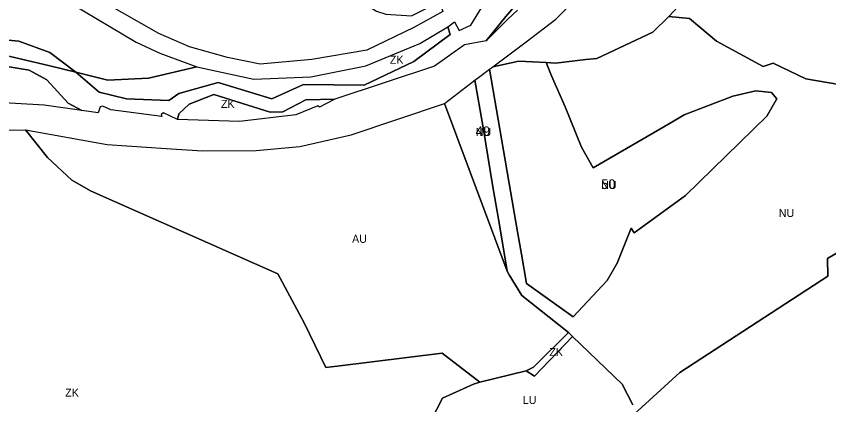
# Model space of a CAD drawing. Extents: x -521261 to -517465, y -1182764 to -1179456.
# Drawn here: x -518710 to -518203, y -1182068 to -1181825 of the extents above; entities that cross this region are included whole.
import ezdxf

# ---------------------------------------------------------------- set-up
doc = ezdxf.new("R2010")
doc.units = 0
for name, color, linetype in [('90640013', 7, 'Continuous'), ('90710013', 7, 'Continuous'), ('90730013', 7, 'Continuous'), ('90730023', 7, 'Continuous'), ('90750013', 7, 'Continuous'), ('90770013', 7, 'Continuous'), ('ID_navrh', 7, 'Continuous')]:
    doc.layers.add(name, color=color, linetype=linetype)

msp = doc.modelspace()

# ---------------------------------------------------------------- linework, layer by layer
at = {"layer": '90640013'}
for points in [[(-518715.11, -1181849.85), (-518689.48, -1181855.99), (-518673.3, -1181859.85), (-518658.65, -1181872.34), (-518641.68, -1181876.61), (-518615.19, -1181877.65), (-518608.89, -1181873.1), (-518588.11, -1181867.31), (-518584.29, -1181866.38), (-518550.76, -1181876.48), (-518531.13, -1181867.61), (-518493.06, -1181867.9), (-518462.19, -1181853.28), (-518439.36, -1181836.36), (-518440.9, -1181831.61), (-518436.68, -1181828.52), (-518433.85, -1181833.87), (-518426.44, -1181830.61), (-518418.2, -1181817.08)], [(-518399.59, -1181819.23), (-518404.75, -1181825.16), (-518417.05, -1181840.21), (-518430.51, -1181842.88), (-518449.2, -1181856.15), (-518511.46, -1181876.67), (-518529.58, -1181877.23), (-518543.87, -1181884.74), (-518551.9, -1181884.77), (-518587.12, -1181873.73), (-518602.51, -1181879.76), (-518608.97, -1181885.92), (-518609.76, -1181889.48), (-518618.56, -1181885.25), (-518619.93, -1181886.24), (-518619.44, -1181887.57), (-518651.41, -1181883.48), (-518656.4, -1181881.12), (-518658.07, -1181881.5), (-518659.19, -1181885.17), (-518669.46, -1181883.83), (-518678.12, -1181879.19), (-518691.4, -1181864.63), (-518702.42, -1181858.59), (-518732.72, -1181853.68)]]:
    msp.add_lwpolyline(points, dxfattribs=at)
at = {"layer": '90710013'}
for points in [[(-518302.96, -1181825.14), (-518312.78, -1181834.79), (-518347.83, -1181851.39), (-518354.74, -1181851.96), (-518373.71, -1181854.29), (-518379.46, -1181853.84), (-518396.5, -1181852.96), (-518412.79, -1181856.47), (-518392.04, -1181840.87), (-518373.39, -1181826.78), (-518345.1, -1181798.17), (-518320.12, -1181766.51), (-518297.97, -1181731.65), (-518284.29, -1181709.64), (-518257.78, -1181667.72), (-518268.81, -1181694.86), (-518271.03, -1181704.12), (-518273.51, -1181713.67), (-518287.7, -1181797.29), (-518296.94, -1181818.88)], [(-518673.3, -1181859.85), (-518653.23, -1181864.79), (-518627.84, -1181863.67), (-518597.74, -1181856.58), (-518562.08, -1181864.17), (-518526.41, -1181862.85), (-518492.11, -1181855.83), (-518458.32, -1181841.87), (-518440.9, -1181831.61), (-518439.36, -1181836.36), (-518462.19, -1181853.28), (-518493.06, -1181867.9), (-518531.13, -1181867.61), (-518550.76, -1181876.48), (-518584.29, -1181866.38), (-518588.11, -1181867.31), (-518608.89, -1181873.1), (-518615.19, -1181877.65), (-518641.68, -1181876.61), (-518658.65, -1181872.34)], [(-518535.85, -1181886.47), (-518570.95, -1181890.66), (-518609.76, -1181889.48), (-518608.97, -1181885.92), (-518602.51, -1181879.76), (-518587.12, -1181873.73), (-518551.9, -1181884.77), (-518543.87, -1181884.74), (-518529.58, -1181877.23), (-518511.46, -1181876.67), (-518517.15, -1181879.72), (-518520.95, -1181881.69), (-518522.17, -1181880.83)], [(-518365.6, -1182022.45), (-518363.045, -1182024.91), (-518386.67, -1182049.7), (-518391.97, -1182046.38), (-518387.41, -1182044.05)]]:
    msp.add_lwpolyline(points, close=True, dxfattribs=at)
for points in [[(-518783.87, -1181833.43), (-518708.84, -1181840.52), (-518689.43, -1181847.62), (-518673.3, -1181859.85), (-518689.48, -1181855.99), (-518715.11, -1181849.85)], [(-518928.06, -1182074.15), (-518913.53, -1182057.93), (-518918.106, -1182050.945), (-518903.79, -1182038.57), (-518884.14, -1182023.3), (-518858.18, -1181999.19), (-518833.62, -1181978.44), (-518841.96, -1181963.21), (-518740.3, -1181896.33), (-518704.59, -1181895.96), (-518690.9, -1181913.09), (-518675.7, -1181927.23), (-518663.75, -1181934.22), (-518547.12, -1181985.79), (-518530.56, -1182016.35), (-518517.09, -1182044.24), (-518510.09, -1182043.38), (-518444.47, -1182035.28), (-518420.88, -1182053.43), (-518424.84, -1182054.69), (-518444.19, -1182063.4), (-518462.82, -1182099.41)]]:
    msp.add_lwpolyline(points, dxfattribs=at)
at = {"layer": '90730013'}
for points in [[(-518325.37, -1182067.68), (-518332.06, -1182054.74), (-518363.045, -1182024.91), (-518365.6, -1182022.45), (-518394.72, -1181999.37), (-518402.62, -1181986.36), (-518403.86, -1181984.22), (-518408.71, -1181955.21), (-518412.94, -1181930.27), (-518418.91, -1181894.43), (-518423.93, -1181864.88), (-518420.92, -1181862.58), (-518414.92, -1181857.99), (-518397.34, -1181959.64), (-518394.95, -1181973.55), (-518391.67, -1181991.87), (-518362.72, -1182012.59), (-518341.38, -1181989.87), (-518335.14, -1181979.1), (-518326.35, -1181957.27), (-518324.52, -1181960.18), (-518292.42, -1181936.84), (-518241.66, -1181887.31), (-518235.39, -1181876.59), (-518238.76, -1181872.67), (-518248.46, -1181871.63), (-518262.89, -1181874.89), (-518293.39, -1181886.48), (-518302.11, -1181891.7), (-518350.22, -1181919.64), (-518357.49, -1181906.63), (-518367.68, -1181881.56), (-518376.06, -1181862.1), (-518379.46, -1181853.84), (-518373.71, -1181854.29), (-518354.74, -1181851.96), (-518347.83, -1181851.39), (-518312.78, -1181834.79), (-518302.96, -1181825.14), (-518289.97, -1181826.31), (-518283.47, -1181831.75), (-518273.09, -1181840.42), (-518243.96, -1181856.31), (-518237.7, -1181854.2), (-518217.29, -1181863.99), (-518196.73, -1181867.61)], [(-518167.73, -1181955), (-518203.86, -1181976.19), (-518203.6, -1181987.3), (-518296.03, -1182047.39), (-518326.89, -1182075.42)]]:
    msp.add_lwpolyline(points, dxfattribs=at)
at = {"layer": '90730023'}
for points in [[(-518412.79, -1181856.47), (-518396.5, -1181852.96), (-518379.46, -1181853.84), (-518376.06, -1181862.1), (-518367.68, -1181881.56), (-518357.49, -1181906.63), (-518350.22, -1181919.64), (-518302.11, -1181891.7), (-518293.39, -1181886.48), (-518262.89, -1181874.89), (-518248.46, -1181871.63), (-518238.76, -1181872.67), (-518235.39, -1181876.59), (-518241.66, -1181887.31), (-518292.42, -1181936.84), (-518324.52, -1181960.18), (-518326.35, -1181957.27), (-518335.14, -1181979.1), (-518341.38, -1181989.87), (-518362.72, -1182012.59), (-518391.67, -1181991.87), (-518394.95, -1181973.55), (-518397.34, -1181959.64), (-518414.92, -1181857.99)], [(-518403.86, -1181984.22), (-518443.06, -1181879.44), (-518423.93, -1181864.88), (-518418.91, -1181894.43), (-518412.94, -1181930.27), (-518408.71, -1181955.21)]]:
    msp.add_lwpolyline(points, close=True, dxfattribs=at)
at = {"layer": '90750013'}
for points in [[(-518196.73, -1181867.61), (-518217.29, -1181863.99), (-518237.7, -1181854.2), (-518243.96, -1181856.31), (-518273.09, -1181840.42), (-518283.47, -1181831.75), (-518289.97, -1181826.31), (-518302.96, -1181825.14), (-518296.94, -1181818.88), (-518287.7, -1181797.29), (-518273.51, -1181713.67), (-518271.03, -1181704.12), (-518268.81, -1181694.86), (-518257.78, -1181667.72), (-518223.62, -1181626.24), (-518210.43, -1181608.65), (-518201.08, -1181598.66)], [(-518397.42, -1181821.23), (-518403.42, -1181826.84), (-518417.05, -1181840.21), (-518404.75, -1181825.16), (-518399.59, -1181819.23)], [(-518732.72, -1181853.68), (-518702.42, -1181858.59), (-518691.4, -1181864.63), (-518678.12, -1181879.19), (-518669.46, -1181883.83), (-518692.94, -1181880.52), (-518725.49, -1181878.51)], [(-518326.89, -1182075.42), (-518296.03, -1182047.39), (-518203.6, -1181987.3), (-518203.86, -1181976.19), (-518167.73, -1181955)]]:
    msp.add_lwpolyline(points, dxfattribs=at)
for points in [[(-518621.41, -1181835.63), (-518677.32, -1181803.77), (-518693.056, -1181798.326), (-518689.53, -1181773.67), (-518658.29, -1181781.74), (-518631.48, -1181785.91), (-518611.95, -1181784.61), (-518573.313, -1181774.703), (-518573.313, -1181774.703), (-518531.34, -1181799.45), (-518504.33, -1181809.73), (-518485.49, -1181821.82), (-518479.61, -1181823.57), (-518463.58, -1181824.77), (-518446.06, -1181816.02), (-518444.06, -1181822.06), (-518462.21, -1181832.05), (-518491.58, -1181846.12), (-518525.9, -1181851.87), (-518558.11, -1181854.84), (-518578.55, -1181850.79), (-518602.16, -1181844.15)], [(-518620.85, -1181848.06), (-518597.74, -1181856.58), (-518627.84, -1181863.67), (-518653.23, -1181864.79), (-518673.3, -1181859.85), (-518689.43, -1181847.62), (-518708.84, -1181840.52), (-518783.87, -1181833.43), (-518802.16, -1181829.32), (-518822.01, -1181813.66), (-518823.91, -1181809.28), (-518803.25, -1181801.73), (-518772.27, -1181796.81), (-518760.7, -1181796.26), (-518739.83, -1181797.72), (-518713.38, -1181802.54), (-518694.2, -1181808.7), (-518676.08, -1181816.9), (-518635.51, -1181841.21)], [(-518391.97, -1182046.38), (-518420.88, -1182053.43), (-518444.47, -1182035.28), (-518510.09, -1182043.38), (-518517.09, -1182044.24), (-518530.56, -1182016.35), (-518547.12, -1181985.79), (-518663.75, -1181934.22), (-518675.7, -1181927.23), (-518690.9, -1181913.09), (-518704.59, -1181895.96), (-518653.59, -1181905.09), (-518616.77, -1181907.64), (-518594.09, -1181908.98), (-518560.65, -1181908.71), (-518533.23, -1181906.38), (-518501.17, -1181898.93), (-518443.06, -1181879.44), (-518403.86, -1181984.22), (-518402.62, -1181986.36), (-518394.72, -1181999.37), (-518365.6, -1182022.45), (-518387.41, -1182044.05)]]:
    msp.add_lwpolyline(points, close=True, dxfattribs=at)
at = {"layer": '90770013'}
msp.add_lwpolyline([(-518462.82, -1182099.41), (-518444.19, -1182063.4), (-518424.84, -1182054.69), (-518420.88, -1182053.43), (-518391.97, -1182046.38), (-518386.67, -1182049.7), (-518363.045, -1182024.91), (-518332.06, -1182054.74), (-518325.37, -1182067.68)], dxfattribs=at)

# ---------------------------------------------------------------- texts
at = {"layer": '90710013'}
for rotation, p in [(0, (-518477.123, -1181854.63)), (360, (-518582.589, -1181882.195)), (360, (-518377.508, -1182037.164)), (0, (-518679.884, -1182062.485))]:
    msp.add_text('ZK', height=5, rotation=rotation, dxfattribs=at).set_placement(p)
at = {"layer": '90730013'}
msp.add_text('NU', height=5, rotation=360, dxfattribs=at).set_placement((-518234.209, -1181950.28))
at = {"layer": '90730023'}
for rotation, p in [(360, (-518423.46, -1181899.738)), (0, (-518345.12, -1181932.775))]:
    msp.add_text('NU', height=5, rotation=rotation, dxfattribs=at).set_placement(p)
at = {"layer": '90750013'}
msp.add_text('AU', height=5, dxfattribs=at).set_placement((-518500.703, -1181966.435))
at = {"layer": '90770013'}
msp.add_text('LU', height=5, rotation=360, dxfattribs=at).set_placement((-518394.095, -1182067.097))
at = {"layer": 'ID_navrh'}
for s, rotation, p in [('49', 0, (-518423.46, -1181899.738)), ('50', 360, (-518345.12, -1181932.775))]:
    msp.add_text(s, height=6, rotation=rotation, dxfattribs=at).set_placement(p)

doc.saveas('drawing.dxf')
